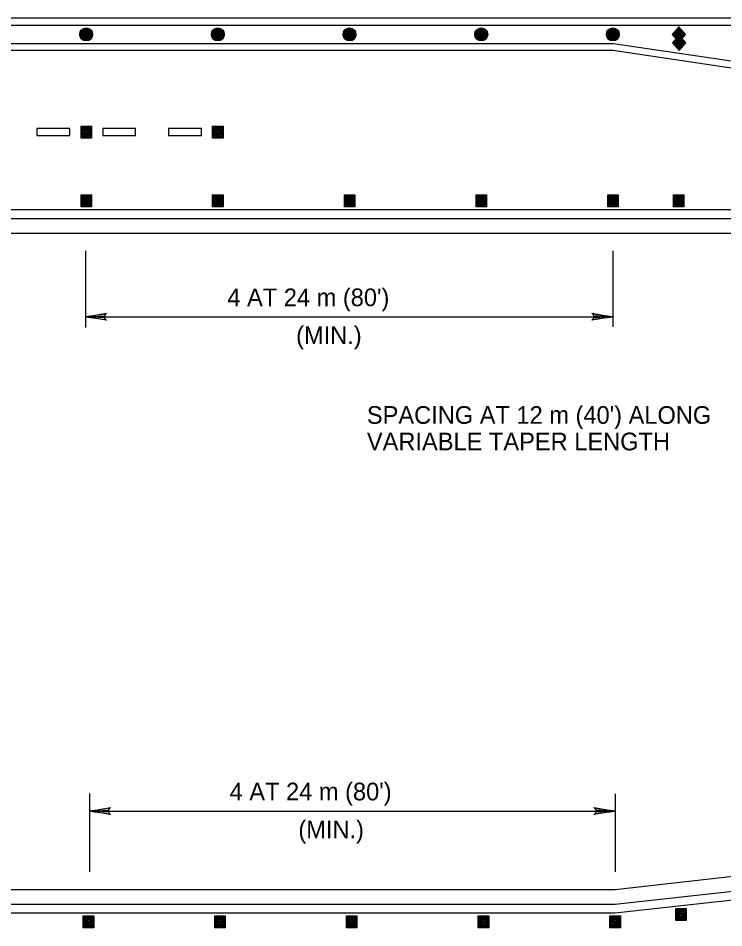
# Model space of a CAD drawing. Extents: x 639362 to 641108, y 298458 to 299646.
# Drawn here: x 639484.5 to 639604.4, y 298617.7 to 298772.2 of the extents above; entities that cross this region are included whole.
import ezdxf

# ---------------------------------------------------------------- set-up
doc = ezdxf.new("R2010")
doc.units = 0
doc.layers.add('2', color=7, linetype='Continuous')
doc.layers.add('3', color=7, linetype='Continuous')

# ---------------------------------------------------------------- blocks, each defined once
blk = doc.blocks.new('RARROW')
at = {"layer": '3'}
blk.add_lwpolyline([(-2.2695, 0.285), (-2.184875, 0.12075), (0, 0), (-2.2695, 0.285), (-2.38575, 0.384625), (0, 0), (-2.183125, -0.108), (-2.262875, -0.2705), (0, 0), (-2.38575, -0.379125), (-2.262875, -0.2705)], dxfattribs=at)

msp = doc.modelspace()

# ---------------------------------------------------------------- linework, layer by layer
at = {"layer": '2'}
for p, q in [((639719.73, 298772.16), (639431.25, 298772.16)), ((639431.25, 298770.96), (639719.64, 298770.96)), ((639596.74, 298770.67), (639595.61, 298769.37)), ((639596.84, 298770.55), (639595.73, 298769.27)), ((639596.95, 298770.43), (639595.82, 298769.13)), ((639597.05, 298770.31), (639595.92, 298769.01)), ((639597.16, 298770.19), (639596.03, 298768.89)), ((639596.34, 298770.21), (639597.47, 298768.92)), ((639596.45, 298770.33), (639597.57, 298769.04)), ((639596.55, 298770.45), (639597.68, 298769.16)), ((639596.65, 298770.57), (639597.78, 298769.28)), ((639597.87, 298769.37), (639596.74, 298770.67)), ((639596.74, 298770.67), (639596.74, 298768.08)), ((639595.61, 298769.37), (639596.74, 298768.08)), ((639595.61, 298769.37), (639597.87, 298769.37)), ((639596.77, 298769.27), (639595.64, 298767.97)), ((639595.71, 298769.49), (639596.84, 298768.2)), ((639596.87, 298769.15), (639595.76, 298767.87)), ((639595.82, 298769.61), (639596.95, 298768.32)), ((639596.98, 298769.03), (639595.85, 298767.73)), ((639595.92, 298769.73), (639597.05, 298768.44)), ((639597.08, 298768.91), (639595.96, 298767.61)), ((639596.03, 298769.85), (639597.16, 298768.56)), ((639597.19, 298768.79), (639596.06, 298767.49)), ((639597.26, 298770.07), (639596.13, 298768.77)), ((639596.13, 298769.97), (639597.26, 298768.68)), ((639597.29, 298768.67), (639596.17, 298767.37)), ((639596.24, 298770.09), (639597.36, 298768.8)), ((639597.36, 298769.95), (639596.24, 298768.65)), ((639596.27, 298768.69), (639597.4, 298767.4)), ((639597.47, 298769.83), (639596.34, 298768.53)), ((639596.37, 298768.81), (639597.5, 298767.52)), ((639597.57, 298769.71), (639596.45, 298768.41)), ((639596.48, 298768.93), (639597.61, 298767.64)), ((639597.68, 298769.59), (639596.55, 298768.29)), ((639596.58, 298769.05), (639597.71, 298767.76)), ((639597.78, 298769.47), (639596.65, 298768.17)), ((639596.69, 298769.17), (639597.81, 298767.88)), ((639596.74, 298768.08), (639597.87, 298769.37)), ((639597.9, 298767.97), (639596.77, 298769.27)), ((639596.77, 298769.27), (639596.77, 298766.68)), ((639431.25, 298767.85), (639585.61, 298767.85)), ((639585.61, 298767.85), (639663.88, 298756.28)), ((639595.64, 298767.97), (639596.77, 298766.68)), ((639595.64, 298767.97), (639597.9, 298767.97)), ((639595.75, 298768.09), (639596.87, 298766.8)), ((639595.85, 298768.21), (639596.98, 298766.92)), ((639595.96, 298768.33), (639597.08, 298767.04)), ((639596.06, 298768.45), (639597.19, 298767.16)), ((639596.17, 298768.57), (639597.29, 298767.28)), ((639597.4, 298768.55), (639596.27, 298767.25)), ((639597.5, 298768.43), (639596.37, 298767.13)), ((639597.61, 298768.31), (639596.48, 298767.01)), ((639597.71, 298768.19), (639596.58, 298766.89)), ((639597.81, 298768.07), (639596.69, 298766.77)), ((639596.77, 298766.68), (639597.9, 298767.97)), ((639585.52, 298766.65), (639431.25, 298766.65)), ((639663.79, 298755.08), (639585.52, 298766.65)), ((639487.66, 298753.41), (639487.66, 298752.21)), ((639493.25, 298753.41), (639487.66, 298753.41)), ((639493.25, 298752.21), (639493.25, 298753.41)), ((639495.17, 298753.83), (639496.94, 298753.83)), ((639495.17, 298751.79), (639495.17, 298753.83)), ((639495.34, 298753.65), (639496.76, 298753.65)), ((639495.34, 298751.96), (639495.34, 298753.65)), ((639495.52, 298753.47), (639496.59, 298753.47)), ((639495.52, 298752.14), (639495.52, 298753.47)), ((639495.7, 298752.32), (639495.7, 298753.29)), ((639495.7, 298753.29), (639496.41, 298753.29)), ((639496.41, 298753.29), (639496.41, 298752.32)), ((639496.59, 298753.47), (639496.59, 298752.14)), ((639496.76, 298753.65), (639496.76, 298751.96)), ((639496.94, 298753.83), (639496.94, 298751.79)), ((639498.85, 298753.41), (639498.85, 298752.21)), ((639504.44, 298753.41), (639498.85, 298753.41)), ((639504.44, 298752.21), (639504.44, 298753.41)), ((639510.03, 298753.41), (639510.03, 298752.21)), ((639515.62, 298753.41), (639510.03, 298753.41)), ((639515.62, 298752.21), (639515.62, 298753.41)), ((639517.53, 298753.83), (639519.31, 298753.83)), ((639517.53, 298751.79), (639517.53, 298753.83)), ((639517.71, 298753.65), (639519.13, 298753.65)), ((639517.71, 298751.96), (639517.71, 298753.65)), ((639517.89, 298753.47), (639518.95, 298753.47)), ((639517.89, 298752.14), (639517.89, 298753.47)), ((639518.07, 298752.32), (639518.07, 298753.29)), ((639518.07, 298753.29), (639518.77, 298753.29)), ((639518.77, 298753.29), (639518.77, 298752.32)), ((639518.95, 298753.47), (639518.95, 298752.14)), ((639519.13, 298753.65), (639519.13, 298751.96)), ((639519.31, 298753.83), (639519.31, 298751.79)), ((639487.66, 298752.21), (639493.25, 298752.21)), ((639496.94, 298751.79), (639495.17, 298751.79)), ((639496.76, 298751.96), (639495.34, 298751.96)), ((639496.59, 298752.14), (639495.52, 298752.14)), ((639496.41, 298752.32), (639495.7, 298752.32)), ((639495.88, 298753.12), (639496.23, 298753.12)), ((639495.88, 298752.5), (639495.88, 298753.12)), ((639496.23, 298752.5), (639495.88, 298752.5)), ((639496.05, 298752.94), (639496.05, 298752.67)), ((639496.23, 298753.12), (639496.23, 298752.5)), ((639498.85, 298752.21), (639504.44, 298752.21)), ((639510.03, 298752.21), (639515.62, 298752.21)), ((639519.31, 298751.79), (639517.53, 298751.79)), ((639519.13, 298751.96), (639517.71, 298751.96)), ((639518.95, 298752.14), (639517.89, 298752.14)), ((639518.77, 298752.32), (639518.07, 298752.32)), ((639518.24, 298753.12), (639518.6, 298753.12)), ((639518.24, 298752.5), (639518.24, 298753.12)), ((639518.6, 298752.5), (639518.24, 298752.5)), ((639518.42, 298752.94), (639518.42, 298752.67)), ((639518.6, 298753.12), (639518.6, 298752.5)), ((639495.17, 298742.18), (639496.94, 298742.18)), ((639495.17, 298740.14), (639495.17, 298742.18)), ((639495.34, 298742), (639496.76, 298742)), ((639495.34, 298740.32), (639495.34, 298742)), ((639495.52, 298741.82), (639496.59, 298741.82)), ((639495.52, 298740.5), (639495.52, 298741.82)), ((639495.7, 298740.67), (639495.7, 298741.65)), ((639495.7, 298741.65), (639496.41, 298741.65)), ((639495.88, 298741.47), (639496.23, 298741.47)), ((639495.88, 298740.85), (639495.88, 298741.47)), ((639496.23, 298740.85), (639495.88, 298740.85)), ((639496.05, 298741.29), (639496.05, 298741.03)), ((639496.23, 298741.47), (639496.23, 298740.85)), ((639496.41, 298741.65), (639496.41, 298740.67)), ((639496.59, 298741.82), (639496.59, 298740.5)), ((639496.76, 298742), (639496.76, 298740.32)), ((639496.94, 298742.18), (639496.94, 298740.14)), ((639517.53, 298742.18), (639519.31, 298742.18)), ((639517.53, 298740.14), (639517.53, 298742.18)), ((639517.71, 298742), (639519.13, 298742)), ((639517.71, 298740.32), (639517.71, 298742)), ((639517.89, 298741.82), (639518.95, 298741.82)), ((639517.89, 298740.5), (639517.89, 298741.82)), ((639518.07, 298740.67), (639518.07, 298741.65)), ((639518.07, 298741.65), (639518.77, 298741.65)), ((639518.24, 298741.47), (639518.6, 298741.47)), ((639518.24, 298740.85), (639518.24, 298741.47)), ((639518.6, 298740.85), (639518.24, 298740.85)), ((639518.42, 298741.29), (639518.42, 298741.03)), ((639518.6, 298741.47), (639518.6, 298740.85)), ((639518.77, 298741.65), (639518.77, 298740.67)), ((639518.95, 298741.82), (639518.95, 298740.5)), ((639519.13, 298742), (639519.13, 298740.32)), ((639519.31, 298742.18), (639519.31, 298740.14)), ((639539.9, 298742.18), (639541.68, 298742.18)), ((639539.9, 298740.14), (639539.9, 298742.18)), ((639540.08, 298742), (639541.5, 298742)), ((639540.08, 298740.32), (639540.08, 298742)), ((639540.26, 298741.82), (639541.32, 298741.82)), ((639540.26, 298740.5), (639540.26, 298741.82)), ((639540.43, 298740.67), (639540.43, 298741.65)), ((639540.43, 298741.65), (639541.14, 298741.65)), ((639540.61, 298741.47), (639540.97, 298741.47)), ((639540.61, 298740.85), (639540.61, 298741.47)), ((639540.97, 298740.85), (639540.61, 298740.85)), ((639540.79, 298741.29), (639540.79, 298741.03)), ((639540.97, 298741.47), (639540.97, 298740.85)), ((639541.14, 298741.65), (639541.14, 298740.67)), ((639541.32, 298741.82), (639541.32, 298740.5)), ((639541.5, 298742), (639541.5, 298740.32)), ((639541.68, 298742.18), (639541.68, 298740.14)), ((639562.27, 298742.18), (639564.04, 298742.18)), ((639562.27, 298740.14), (639562.27, 298742.18)), ((639562.45, 298742), (639563.86, 298742)), ((639562.45, 298740.32), (639562.45, 298742)), ((639562.62, 298741.82), (639563.69, 298741.82)), ((639562.62, 298740.5), (639562.62, 298741.82)), ((639562.8, 298740.67), (639562.8, 298741.65)), ((639562.8, 298741.65), (639563.51, 298741.65)), ((639562.98, 298741.47), (639563.33, 298741.47)), ((639562.98, 298740.85), (639562.98, 298741.47)), ((639563.33, 298740.85), (639562.98, 298740.85)), ((639563.15, 298741.29), (639563.15, 298741.03)), ((639563.33, 298741.47), (639563.33, 298740.85)), ((639563.51, 298741.65), (639563.51, 298740.67)), ((639563.69, 298741.82), (639563.69, 298740.5)), ((639563.86, 298742), (639563.86, 298740.32)), ((639564.04, 298742.18), (639564.04, 298740.14)), ((639584.64, 298742.18), (639586.41, 298742.18)), ((639584.64, 298740.14), (639584.64, 298742.18)), ((639584.81, 298742), (639586.23, 298742)), ((639584.81, 298740.32), (639584.81, 298742)), ((639584.99, 298741.82), (639586.06, 298741.82)), ((639584.99, 298740.5), (639584.99, 298741.82)), ((639585.17, 298740.67), (639585.17, 298741.65)), ((639585.17, 298741.65), (639585.88, 298741.65)), ((639585.35, 298741.47), (639585.7, 298741.47)), ((639585.35, 298740.85), (639585.35, 298741.47)), ((639585.7, 298740.85), (639585.35, 298740.85)), ((639585.52, 298741.29), (639585.52, 298741.03)), ((639585.7, 298741.47), (639585.7, 298740.85)), ((639585.88, 298741.65), (639585.88, 298740.67)), ((639586.06, 298741.82), (639586.06, 298740.5)), ((639586.23, 298742), (639586.23, 298740.32)), ((639586.41, 298742.18), (639586.41, 298740.14)), ((639595.82, 298742.18), (639597.59, 298742.18)), ((639595.82, 298740.14), (639595.82, 298742.18)), ((639596, 298742), (639597.42, 298742)), ((639596, 298740.32), (639596, 298742)), ((639596.17, 298741.82), (639597.24, 298741.82)), ((639596.17, 298740.5), (639596.17, 298741.82)), ((639596.35, 298740.67), (639596.35, 298741.65)), ((639596.35, 298741.65), (639597.06, 298741.65)), ((639596.53, 298741.47), (639596.88, 298741.47)), ((639596.53, 298740.85), (639596.53, 298741.47)), ((639596.88, 298740.85), (639596.53, 298740.85)), ((639596.7, 298741.29), (639596.7, 298741.03)), ((639596.88, 298741.47), (639596.88, 298740.85)), ((639597.06, 298741.65), (639597.06, 298740.67)), ((639597.24, 298741.82), (639597.24, 298740.5)), ((639597.42, 298742), (639597.42, 298740.32)), ((639597.59, 298742.18), (639597.59, 298740.14)), ((639431.35, 298739.66), (639952.74, 298739.66)), ((639496.94, 298740.14), (639495.17, 298740.14)), ((639496.76, 298740.32), (639495.34, 298740.32)), ((639496.59, 298740.5), (639495.52, 298740.5)), ((639496.41, 298740.67), (639495.7, 298740.67)), ((639519.31, 298740.14), (639517.53, 298740.14)), ((639519.13, 298740.32), (639517.71, 298740.32)), ((639518.95, 298740.5), (639517.89, 298740.5)), ((639518.77, 298740.67), (639518.07, 298740.67)), ((639541.68, 298740.14), (639539.9, 298740.14)), ((639541.5, 298740.32), (639540.08, 298740.32)), ((639541.32, 298740.5), (639540.26, 298740.5)), ((639541.14, 298740.67), (639540.43, 298740.67)), ((639564.04, 298740.14), (639562.27, 298740.14)), ((639563.86, 298740.32), (639562.45, 298740.32)), ((639563.69, 298740.5), (639562.62, 298740.5)), ((639563.51, 298740.67), (639562.8, 298740.67)), ((639586.41, 298740.14), (639584.64, 298740.14)), ((639586.23, 298740.32), (639584.81, 298740.32)), ((639586.06, 298740.5), (639584.99, 298740.5)), ((639585.88, 298740.67), (639585.17, 298740.67)), ((639597.59, 298740.14), (639595.82, 298740.14)), ((639597.42, 298740.32), (639596, 298740.32)), ((639597.24, 298740.5), (639596.17, 298740.5)), ((639597.06, 298740.67), (639596.35, 298740.67)), ((639431.35, 298738.16), (639952.74, 298738.16)), ((639431.35, 298735.66), (639952.74, 298735.66)), ((639495.91, 298732.66), (639495.91, 298719.65)), ((639585.52, 298732.66), (639585.52, 298719.73)), ((639495.91, 298721.46), (639585.52, 298721.46)), ((639585.9, 298624.2), (639797.99, 298647.81)), ((639585.9, 298621.7), (639797.99, 298645.31)), ((639585.9, 298620.2), (639797.99, 298643.81)), ((639496.59, 298640.5), (639496.59, 298627.2)), ((639585.9, 298640.42), (639585.9, 298627.2)), ((639496.59, 298637.5), (639585.9, 298637.5)), ((639431.63, 298624.2), (639585.9, 298624.2)), ((639431.63, 298621.7), (639585.9, 298621.7)), ((639596.2, 298620.95), (639597.97, 298620.95)), ((639596.2, 298618.91), (639596.2, 298620.95)), ((639596.37, 298620.77), (639597.79, 298620.77)), ((639596.37, 298619.09), (639596.37, 298620.77)), ((639596.55, 298620.6), (639597.61, 298620.6)), ((639596.55, 298619.27), (639596.55, 298620.6)), ((639596.73, 298619.45), (639596.73, 298620.42)), ((639596.73, 298620.42), (639597.44, 298620.42)), ((639597.44, 298620.42), (639597.44, 298619.45)), ((639597.61, 298620.6), (639597.61, 298619.27)), ((639597.79, 298620.77), (639597.79, 298619.09)), ((639597.97, 298620.95), (639597.97, 298618.91)), ((639431.63, 298620.2), (639585.9, 298620.2)), ((639495.54, 298619.72), (639497.32, 298619.72)), ((639495.54, 298617.68), (639495.54, 298619.72)), ((639495.72, 298619.54), (639497.14, 298619.54)), ((639495.72, 298617.85), (639495.72, 298619.54)), ((639495.9, 298619.36), (639496.96, 298619.36)), ((639495.9, 298618.03), (639495.9, 298619.36)), ((639496.07, 298618.21), (639496.07, 298619.18)), ((639496.07, 298619.18), (639496.78, 298619.18)), ((639496.25, 298619.01), (639496.61, 298619.01)), ((639496.25, 298618.39), (639496.25, 298619.01)), ((639496.43, 298618.83), (639496.43, 298618.56)), ((639496.61, 298619.01), (639496.61, 298618.39)), ((639496.78, 298619.18), (639496.78, 298618.21)), ((639496.96, 298619.36), (639496.96, 298618.03)), ((639497.14, 298619.54), (639497.14, 298617.85)), ((639497.32, 298619.72), (639497.32, 298617.68)), ((639517.91, 298619.72), (639519.68, 298619.72)), ((639517.91, 298617.68), (639517.91, 298619.72)), ((639518.09, 298619.54), (639519.51, 298619.54)), ((639518.09, 298617.85), (639518.09, 298619.54)), ((639518.26, 298619.36), (639519.33, 298619.36)), ((639518.26, 298618.03), (639518.26, 298619.36)), ((639518.44, 298618.21), (639518.44, 298619.18)), ((639518.44, 298619.18), (639519.15, 298619.18)), ((639518.62, 298619.01), (639518.97, 298619.01)), ((639518.62, 298618.39), (639518.62, 298619.01)), ((639518.79, 298618.83), (639518.79, 298618.56)), ((639518.97, 298619.01), (639518.97, 298618.39)), ((639519.15, 298619.18), (639519.15, 298618.21)), ((639519.33, 298619.36), (639519.33, 298618.03)), ((639519.51, 298619.54), (639519.51, 298617.85)), ((639519.68, 298619.72), (639519.68, 298617.68)), ((639540.28, 298619.72), (639542.05, 298619.72)), ((639540.28, 298617.68), (639540.28, 298619.72)), ((639540.45, 298619.54), (639541.87, 298619.54)), ((639540.45, 298617.85), (639540.45, 298619.54)), ((639540.63, 298619.36), (639541.7, 298619.36)), ((639540.63, 298618.03), (639540.63, 298619.36)), ((639540.81, 298618.21), (639540.81, 298619.18)), ((639540.81, 298619.18), (639541.52, 298619.18)), ((639540.99, 298619.01), (639541.34, 298619.01)), ((639540.99, 298618.39), (639540.99, 298619.01)), ((639541.16, 298618.83), (639541.16, 298618.56)), ((639541.34, 298619.01), (639541.34, 298618.39)), ((639541.52, 298619.18), (639541.52, 298618.21)), ((639541.7, 298619.36), (639541.7, 298618.03)), ((639541.87, 298619.54), (639541.87, 298617.85)), ((639542.05, 298619.72), (639542.05, 298617.68)), ((639562.64, 298619.72), (639564.42, 298619.72)), ((639562.64, 298617.68), (639562.64, 298619.72)), ((639562.82, 298619.54), (639564.24, 298619.54)), ((639562.82, 298617.85), (639562.82, 298619.54)), ((639563, 298619.36), (639564.06, 298619.36)), ((639563, 298618.03), (639563, 298619.36)), ((639563.18, 298618.21), (639563.18, 298619.18)), ((639563.18, 298619.18), (639563.89, 298619.18)), ((639563.35, 298619.01), (639563.71, 298619.01)), ((639563.35, 298618.39), (639563.35, 298619.01)), ((639563.53, 298618.83), (639563.53, 298618.56)), ((639563.71, 298619.01), (639563.71, 298618.39)), ((639563.89, 298619.18), (639563.89, 298618.21)), ((639564.06, 298619.36), (639564.06, 298618.03)), ((639564.24, 298619.54), (639564.24, 298617.85)), ((639564.42, 298619.72), (639564.42, 298617.68)), ((639585.01, 298619.72), (639586.79, 298619.72)), ((639585.01, 298617.68), (639585.01, 298619.72)), ((639585.19, 298619.54), (639586.61, 298619.54)), ((639585.19, 298617.85), (639585.19, 298619.54)), ((639585.37, 298619.36), (639586.43, 298619.36)), ((639585.37, 298618.03), (639585.37, 298619.36)), ((639585.54, 298618.21), (639585.54, 298619.18)), ((639585.54, 298619.18), (639586.25, 298619.18)), ((639585.72, 298619.01), (639586.08, 298619.01)), ((639585.72, 298618.39), (639585.72, 298619.01)), ((639585.9, 298618.83), (639585.9, 298618.56)), ((639586.08, 298619.01), (639586.08, 298618.39)), ((639586.25, 298619.18), (639586.25, 298618.21)), ((639586.43, 298619.36), (639586.43, 298618.03)), ((639586.61, 298619.54), (639586.61, 298617.85)), ((639586.79, 298619.72), (639586.79, 298617.68)), ((639597.97, 298618.91), (639596.2, 298618.91)), ((639597.79, 298619.09), (639596.37, 298619.09)), ((639597.61, 298619.27), (639596.55, 298619.27)), ((639597.44, 298619.45), (639596.73, 298619.45)), ((639596.91, 298620.24), (639597.26, 298620.24)), ((639596.91, 298619.62), (639596.91, 298620.24)), ((639597.26, 298619.62), (639596.91, 298619.62)), ((639597.08, 298620.07), (639597.08, 298619.8)), ((639597.26, 298620.24), (639597.26, 298619.62)), ((639497.32, 298617.68), (639495.54, 298617.68)), ((639497.14, 298617.85), (639495.72, 298617.85)), ((639496.96, 298618.03), (639495.9, 298618.03)), ((639496.78, 298618.21), (639496.07, 298618.21)), ((639496.61, 298618.39), (639496.25, 298618.39)), ((639519.68, 298617.68), (639517.91, 298617.68)), ((639519.51, 298617.85), (639518.09, 298617.85)), ((639519.33, 298618.03), (639518.26, 298618.03)), ((639519.15, 298618.21), (639518.44, 298618.21)), ((639518.97, 298618.39), (639518.62, 298618.39)), ((639542.05, 298617.68), (639540.28, 298617.68)), ((639541.87, 298617.85), (639540.45, 298617.85)), ((639541.7, 298618.03), (639540.63, 298618.03)), ((639541.52, 298618.21), (639540.81, 298618.21)), ((639541.34, 298618.39), (639540.99, 298618.39)), ((639564.42, 298617.68), (639562.64, 298617.68)), ((639564.24, 298617.85), (639562.82, 298617.85)), ((639564.06, 298618.03), (639563, 298618.03)), ((639563.89, 298618.21), (639563.18, 298618.21)), ((639563.71, 298618.39), (639563.35, 298618.39)), ((639586.79, 298617.68), (639585.01, 298617.68)), ((639586.61, 298617.85), (639585.19, 298617.85)), ((639586.43, 298618.03), (639585.37, 298618.03)), ((639586.25, 298618.21), (639585.54, 298618.21)), ((639586.08, 298618.39), (639585.72, 298618.39))]:
    msp.add_line(p, q, dxfattribs=at)
for centre, radius in [((639496.04, 298769.4), 1.1), ((639496.04, 298769.4), 1.02), ((639496.04, 298769.4), 0.946), ((639496.04, 298769.4), 0.868), ((639496.04, 298769.4), 0.789), ((639518.41, 298769.4), 1.1), ((639518.41, 298769.4), 1.02), ((639518.41, 298769.4), 0.946), ((639518.41, 298769.4), 0.868), ((639518.41, 298769.4), 0.789), ((639540.78, 298769.4), 1.1), ((639540.78, 298769.4), 1.02), ((639540.78, 298769.4), 0.946), ((639540.78, 298769.4), 0.868), ((639540.78, 298769.4), 0.789), ((639563.16, 298769.4), 1.1), ((639563.16, 298769.4), 1.02), ((639563.16, 298769.4), 0.946), ((639563.16, 298769.4), 0.868), ((639563.16, 298769.4), 0.789), ((639585.51, 298769.4), 1.1), ((639585.51, 298769.4), 1.02), ((639585.51, 298769.4), 0.946), ((639585.51, 298769.4), 0.868), ((639585.51, 298769.4), 0.789), ((639496.04, 298769.4), 0.711), ((639496.04, 298769.4), 0.633), ((639496.04, 298769.4), 0.554), ((639496.04, 298769.4), 0.476), ((639496.04, 298769.4), 0.398), ((639496.04, 298769.4), 0.32), ((639496.04, 298769.4), 0.241), ((639496.04, 298769.4), 0.163), ((639496.04, 298769.4), 0.0846), ((639518.41, 298769.4), 0.711), ((639518.41, 298769.4), 0.633), ((639518.41, 298769.4), 0.554), ((639518.41, 298769.4), 0.476), ((639518.41, 298769.4), 0.398), ((639518.41, 298769.4), 0.32), ((639518.41, 298769.4), 0.241), ((639518.41, 298769.4), 0.163), ((639518.41, 298769.4), 0.0846), ((639540.78, 298769.4), 0.711), ((639540.78, 298769.4), 0.633), ((639540.78, 298769.4), 0.554), ((639540.78, 298769.4), 0.476), ((639540.78, 298769.4), 0.398), ((639540.78, 298769.4), 0.32), ((639540.78, 298769.4), 0.241), ((639540.78, 298769.4), 0.163), ((639540.78, 298769.4), 0.0846), ((639563.16, 298769.4), 0.711), ((639563.16, 298769.4), 0.633), ((639563.16, 298769.4), 0.554), ((639563.16, 298769.4), 0.476), ((639563.16, 298769.4), 0.398), ((639563.16, 298769.4), 0.32), ((639563.16, 298769.4), 0.241), ((639563.16, 298769.4), 0.163), ((639563.16, 298769.4), 0.0846), ((639585.51, 298769.4), 0.711), ((639585.51, 298769.4), 0.633), ((639585.51, 298769.4), 0.554), ((639585.51, 298769.4), 0.476), ((639585.51, 298769.4), 0.398), ((639585.51, 298769.4), 0.32), ((639585.51, 298769.4), 0.241), ((639585.51, 298769.4), 0.163), ((639585.51, 298769.4), 0.0846)]:
    msp.add_circle(centre, radius, dxfattribs=at)

# ---------------------------------------------------------------- block references
at = {"layer": '2', "xscale": 1.5089217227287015, "yscale": 1.5711553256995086, "rotation": 180}
for p in [(639495.91, 298721.46), (639496.59, 298637.5)]:
    msp.add_blockref('RARROW', p, dxfattribs=at)
at = {"layer": '2', "xscale": 1.5089217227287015, "yscale": 1.5711553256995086}
for p in [(639585.52, 298721.46), (639585.9, 298637.5)]:
    msp.add_blockref('RARROW', p, dxfattribs=at)

# ---------------------------------------------------------------- texts
at = {"layer": '2'}
for s, p in [("4 AT 24 m (80')", (639520.03, 298723.25)), ('(MIN.)', (639531.71, 298716.81)), ("SPACING AT 12 m (40') ALONG", (639543.73, 298703.27)), ('VARIABLE TAPER LENGTH', (639543.73, 298698.77)), ("4 AT 24 m (80')", (639520.41, 298639.32)), ('(MIN.)', (639532.09, 298632.89))]:
    msp.add_text(s, height=3, dxfattribs=at).set_placement(p)

doc.saveas('drawing.dxf')
